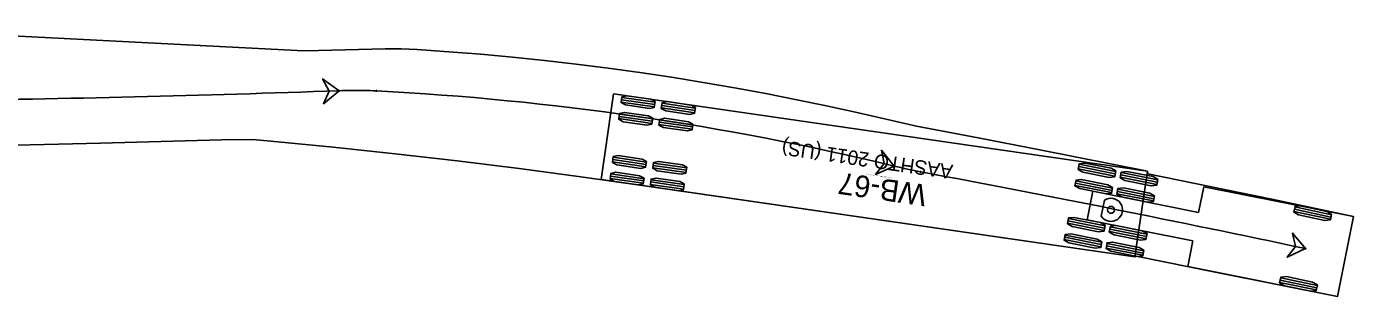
# Model space of a CAD drawing. Extents: x 2175591 to 2194071, y 76570 to 86955.
# Drawn here: x 2192095.4 to 2192225.8, y 86775.5 to 86802 of the extents above; entities that cross this region are included whole.
import ezdxf

# ---------------------------------------------------------------- set-up
doc = ezdxf.new("R2010")
doc.units = 0
doc.layers.add('C-UTIL-STRM-TEXT', color=7, linetype='Continuous')

msp = doc.modelspace()

# ---------------------------------------------------------------- linework, layer by layer
at = {"layer": 'C-UTIL-STRM-TEXT'}
for p, q in [((2192153.08, 86795.37), (2192151.86, 86786.96)), ((2192205.53, 86787.77), (2192153.08, 86795.37)), ((2192157.09, 86794.1), (2192153.82, 86794.57)), ((2192157.12, 86794.32), (2192153.86, 86794.8)), ((2192157.15, 86794.55), (2192153.89, 86795.02)), ((2192161.08, 86793.75), (2192157.81, 86794.22)), ((2192161.11, 86793.98), (2192157.85, 86794.45)), ((2192156.85, 86792.46), (2192153.59, 86792.94)), ((2192156.88, 86792.69), (2192153.62, 86793.16)), ((2192156.92, 86792.92), (2192153.65, 86793.39)), ((2192160.88, 86792.34), (2192157.61, 86792.82)), ((2192161.05, 86793.52), (2192157.78, 86794)), ((2192160.81, 86791.89), (2192157.54, 86792.36)), ((2192160.84, 86792.12), (2192157.58, 86792.59)), ((2192156.27, 86788.45), (2192153, 86788.92)), ((2192156.3, 86788.68), (2192153.04, 86789.15)), ((2192156.24, 86788.22), (2192152.97, 86788.7)), ((2192160.2, 86787.65), (2192156.93, 86788.12)), ((2192160.23, 86787.88), (2192156.96, 86788.35)), ((2192160.26, 86788.1), (2192157, 86788.58)), ((2192202.34, 86787.29), (2192198.74, 86788.01)), ((2192202.38, 86787.52), (2192198.79, 86788.23)), ((2192202.43, 86787.74), (2192198.83, 86788.46)), ((2192206.55, 86786.93), (2192202.95, 86787.64)), ((2192204.31, 86779.36), (2192205.53, 86787.77)), ((2192205.53, 86787.77), (2192205.53, 86787.77)), ((2192151.86, 86786.96), (2192204.31, 86779.36)), ((2192156, 86786.59), (2192152.74, 86787.06)), ((2192156.03, 86786.82), (2192152.77, 86787.29)), ((2192156.07, 86787.04), (2192152.8, 86787.52)), ((2192159.96, 86786.02), (2192156.69, 86786.49)), ((2192159.99, 86786.24), (2192156.73, 86786.72)), ((2192160.03, 86786.47), (2192156.76, 86786.94)), ((2192202.02, 86785.68), (2192198.42, 86786.39)), ((2192202.06, 86785.9), (2192198.46, 86786.62)), ((2192202.11, 86786.13), (2192198.51, 86786.84)), ((2192206.46, 86786.48), (2192202.86, 86787.19)), ((2192206.5, 86786.7), (2192202.91, 86787.42)), ((2192211.07, 86786.26), (2192210.57, 86783.74)), ((2192225.78, 86783.34), (2192211.07, 86786.26)), ((2192200.17, 86785.81), (2192199.61, 86783)), ((2192210.57, 86783.74), (2192200.17, 86785.81)), ((2192201.32, 86784.94), (2192201, 86783.36)), ((2192206.14, 86784.86), (2192202.54, 86785.57)), ((2192206.18, 86785.08), (2192202.58, 86785.8)), ((2192206.22, 86785.31), (2192202.63, 86786.02)), ((2192223.52, 86783.06), (2192219.93, 86783.82)), ((2192223.57, 86783.28), (2192219.98, 86784.04)), ((2192223.62, 86783.51), (2192220.03, 86784.27)), ((2192201.28, 86781.97), (2192197.68, 86782.68)), ((2192201.32, 86782.19), (2192197.73, 86782.9)), ((2192201.37, 86782.41), (2192197.77, 86783.13)), ((2192199.61, 86783), (2192210.01, 86780.93)), ((2192224.22, 86775.49), (2192225.78, 86783.34)), ((2192225.78, 86783.34), (2192225.78, 86783.34)), ((2192200.96, 86780.35), (2192197.36, 86781.06)), ((2192201, 86780.57), (2192197.41, 86781.29)), ((2192201.05, 86780.8), (2192197.45, 86781.51)), ((2192205.4, 86781.15), (2192201.8, 86781.86)), ((2192205.44, 86781.37), (2192201.85, 86782.09)), ((2192205.49, 86781.6), (2192201.89, 86782.31)), ((2192205.08, 86779.53), (2192201.48, 86780.24)), ((2192205.12, 86779.75), (2192201.52, 86780.47)), ((2192205.17, 86779.98), (2192201.57, 86780.69)), ((2192210.01, 86780.93), (2192209.51, 86778.41)), ((2192209.51, 86778.41), (2192224.22, 86775.49)), ((2192222.22, 86776.56), (2192218.64, 86777.32)), ((2192222.13, 86776.12), (2192218.54, 86776.87)), ((2192222.18, 86776.34), (2192218.59, 86777.1))]:
    msp.add_line(p, q, dxfattribs=at)
for points in [[(2192076.16, 86801.98), (2192121.98, 86799.62), (2192122.76, 86799.6), (2192130.62, 86799.79), (2192132.2, 86799.8), (2192133.77, 86799.73), (2192136.9, 86799.51), (2192140.03, 86799.26), (2192143.16, 86798.97), (2192146.29, 86798.65), (2192149.41, 86798.29), (2192152.53, 86797.89), (2192155.65, 86797.46), (2192158.76, 86797), (2192161.87, 86796.5), (2192164.97, 86795.96), (2192168.05, 86795.39), (2192171.09, 86794.8), (2192173.83, 86794.24), (2192176.84, 86793.58), (2192182.83, 86792.2), (2192188.89, 86791.05), (2192194.98, 86789.87), (2192205.53, 86787.77), (2192205.59, 86787.53), (2192211.67, 86786.29), (2192217.75, 86785.04), (2192225.78, 86783.34), (2192224.22, 86775.49), (2192212.37, 86777.84), (2192204.44, 86779.44), (2192204.31, 86779.36), (2192155.9, 86786.37), (2192149.85, 86787.23), (2192143.79, 86788.03), (2192137.71, 86788.79), (2192131.63, 86789.5), (2192125.52, 86790.15), (2192119.41, 86790.74), (2192117.59, 86790.9), (2192114.55, 86790.87), (2192102.66, 86790.54), (2192090.21, 86790.24)], [(2192126.12, 86795.67), (2192126.45, 86795.69), (2192126.78, 86795.7), (2192127.12, 86795.7), (2192127.45, 86795.71), (2192127.78, 86795.71), (2192128.12, 86795.71), (2192128.45, 86795.7), (2192128.78, 86795.7), (2192129.12, 86795.69), (2192129.45, 86795.68), (2192129.78, 86795.66)], [(2192180.65, 86788.29), (2192180.97, 86788.21), (2192181.29, 86788.13), (2192181.62, 86788.06), (2192181.95, 86787.99), (2192182.27, 86787.92), (2192182.6, 86787.85), (2192182.92, 86787.78), (2192183.25, 86787.72)]]:
    msp.add_lwpolyline(points, dxfattribs=at)
for points in [[(2192126.12, 86795.67), (2192124.49, 86796.84), (2192125.12, 86795.64), (2192124.58, 86794.4)], [(2192157.16, 86794.61), (2192157.08, 86794.04), (2192156.6, 86793.93), (2192154.25, 86794.28), (2192153.81, 86794.51), (2192153.9, 86795.08), (2192154.38, 86795.18), (2192156.73, 86794.84)], [(2192161.12, 86794.03), (2192161.04, 86793.47), (2192160.56, 86793.36), (2192158.21, 86793.7), (2192157.77, 86793.94), (2192157.86, 86794.5), (2192158.34, 86794.61), (2192160.69, 86794.27)], [(2192156.93, 86792.97), (2192156.84, 86792.41), (2192156.36, 86792.3), (2192154.01, 86792.64), (2192153.58, 86792.88), (2192153.66, 86793.45), (2192154.14, 86793.55), (2192156.49, 86793.21)], [(2192160.88, 86792.4), (2192160.8, 86791.83), (2192160.32, 86791.73), (2192157.97, 86792.07), (2192157.54, 86792.31), (2192157.62, 86792.87), (2192158.1, 86792.98), (2192160.45, 86792.64)], [(2192156.31, 86788.73), (2192156.23, 86788.17), (2192155.75, 86788.06), (2192153.4, 86788.4), (2192152.96, 86788.64), (2192153.05, 86789.21), (2192153.53, 86789.31), (2192155.88, 86788.97)], [(2192180.65, 86788.29), (2192179.39, 86789.84), (2192179.67, 86788.52), (2192178.82, 86787.47)], [(2192156.07, 86787.1), (2192155.99, 86786.53), (2192155.51, 86786.43), (2192153.16, 86786.77), (2192152.73, 86787.01), (2192152.81, 86787.57), (2192153.29, 86787.68), (2192155.64, 86787.34)], [(2192160.27, 86788.16), (2192160.19, 86787.59), (2192159.71, 86787.49), (2192157.35, 86787.83), (2192156.92, 86788.07), (2192157, 86788.63), (2192157.49, 86788.74), (2192159.84, 86788.4)], [(2192202.44, 86787.8), (2192202.33, 86787.24), (2192201.79, 86787.17), (2192199.2, 86787.68), (2192198.73, 86787.95), (2192198.84, 86788.51), (2192199.38, 86788.58), (2192201.97, 86788.07)], [(2192206.56, 86786.98), (2192206.45, 86786.42), (2192205.91, 86786.35), (2192203.32, 86786.87), (2192202.85, 86787.13), (2192202.96, 86787.7), (2192203.5, 86787.76), (2192206.09, 86787.25)], [(2192160.03, 86786.53), (2192159.95, 86785.96), (2192159.47, 86785.86), (2192157.12, 86786.2), (2192156.69, 86786.43), (2192156.77, 86787), (2192157.25, 86787.1), (2192159.6, 86786.76)], [(2192202.12, 86786.18), (2192202.01, 86785.62), (2192201.47, 86785.55), (2192198.88, 86786.07), (2192198.41, 86786.34), (2192198.52, 86786.9), (2192199.06, 86786.97), (2192201.65, 86786.45)], [(2192206.24, 86785.36), (2192206.12, 86784.8), (2192205.59, 86784.73), (2192203, 86785.25), (2192202.53, 86785.52), (2192202.64, 86786.08), (2192203.18, 86786.15), (2192205.77, 86785.63)], [(2192223.63, 86783.56), (2192223.51, 86783), (2192222.97, 86782.94), (2192220.39, 86783.49), (2192219.92, 86783.76), (2192220.04, 86784.32), (2192220.58, 86784.39), (2192223.16, 86783.84)], [(2192201.38, 86782.47), (2192201.27, 86781.91), (2192200.73, 86781.84), (2192198.14, 86782.36), (2192197.67, 86782.62), (2192197.78, 86783.19), (2192198.32, 86783.25), (2192200.91, 86782.74)], [(2192205.5, 86781.65), (2192205.39, 86781.09), (2192204.85, 86781.02), (2192202.26, 86781.54), (2192201.79, 86781.81), (2192201.9, 86782.37), (2192202.44, 86782.44), (2192205.03, 86781.92)], [(2192201.06, 86780.85), (2192200.95, 86780.29), (2192200.41, 86780.22), (2192197.82, 86780.74), (2192197.35, 86781.01), (2192197.46, 86781.57), (2192198, 86781.64), (2192200.59, 86781.12)], [(2192221.08, 86780.19), (2192219.78, 86781.71), (2192220.1, 86780.4), (2192219.27, 86779.33)], [(2192205.18, 86780.03), (2192205.07, 86779.47), (2192204.53, 86779.4), (2192201.94, 86779.92), (2192201.47, 86780.19), (2192201.58, 86780.75), (2192202.12, 86780.82), (2192204.71, 86780.3)], [(2192222.24, 86776.62), (2192222.12, 86776.06), (2192221.58, 86776), (2192219, 86776.54), (2192218.53, 86776.82), (2192218.65, 86777.38), (2192219.19, 86777.44), (2192221.77, 86776.89)]]:
    msp.add_lwpolyline(points, close=True, dxfattribs=at)
for centre, radius in [((2192126.12, 86795.67), 0.0417), ((2192126.12, 86795.67), 0.0417), ((2192129.78, 86795.66), 0.0417), ((2192129.78, 86795.66), 0.0417), ((2192180.65, 86788.29), 0.0417), ((2192180.65, 86788.29), 0.0417), ((2192183.25, 86787.72), 0.0417), ((2192183.25, 86787.72), 0.0417), ((2192201.95, 86783.99), 0.34), ((2192221.08, 86780.19), 0.0417)]:
    msp.add_circle(centre, radius, dxfattribs=at)
for centre, radius, start, end in [((2192061.95, 88612.05), 1817.51, 270.75542, 272.02321), ((2192115.63, 86519.03), 276.99, 76.4256, 87.0718), ((2191893.46, 85232.78), 1581.71, 78.04562, 79.44279), ((2192201.95, 86783.99), 1.14, 213.7576, 123.7576)]:
    msp.add_arc(centre, radius, start, end, dxfattribs=at)

# ---------------------------------------------------------------- texts
for s, height, p in [('AASHTO 2011 (US)', 1.4167, (2192186.49, 86788.39)), ('WB-67', 2.125, (2192183.93, 86786.43)), ('(c) 2019 Transoft Solutions, Inc. All rights reserved.', 0.085, (2192180.42, 86787.16))]:
    msp.add_text(s, height=height, rotation=171.7534, dxfattribs=at).set_placement(p)

doc.saveas('drawing.dxf')
